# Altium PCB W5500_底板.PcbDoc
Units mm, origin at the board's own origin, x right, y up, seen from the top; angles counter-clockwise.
Board outline 58.8 x 115.4 mm, 2 copper layers (Top Layer, Bottom Layer); 79 components, 82 nets, 337 pads, 77 vias.
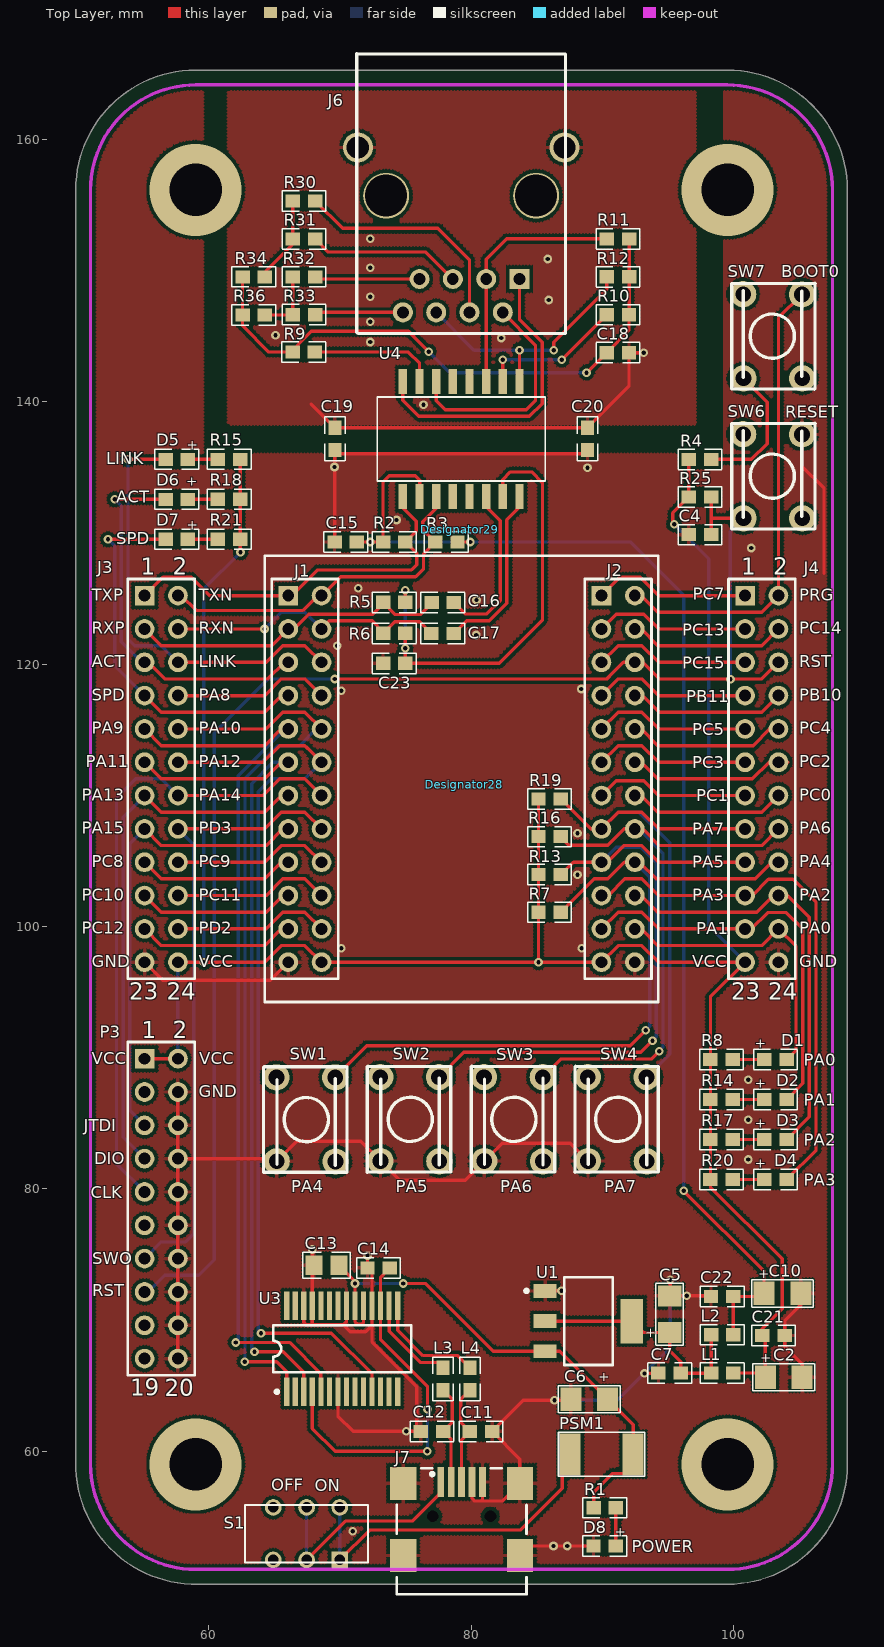
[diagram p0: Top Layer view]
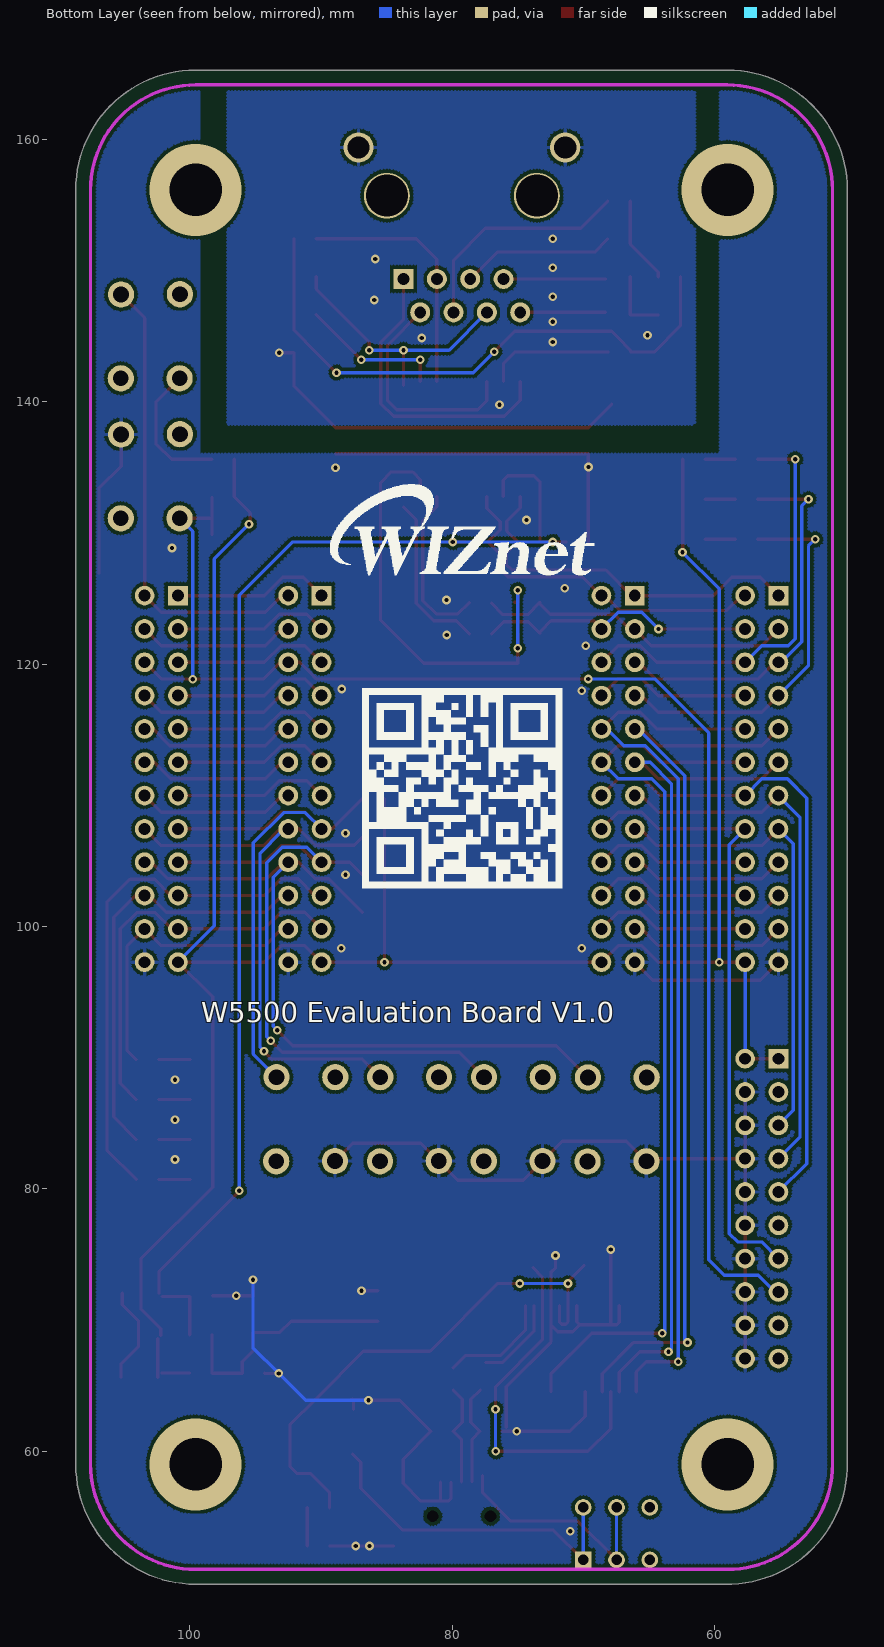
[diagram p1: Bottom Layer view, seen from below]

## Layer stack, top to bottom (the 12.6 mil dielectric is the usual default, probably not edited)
Top Layer: signal copper 0.0356
Dielectric: dielectric 0.32, FR-4, Dk 4.8
Bottom Layer: signal copper 0.0356

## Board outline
58.674,49.878 cw(c59,59) 49.878,58.674 cw(c50,58.712) 49.873,58.712 49.873,156.15 cw(c59,156.15) 59,165.277 99.55,165.277 cw(c99.55,156.15) 108.677,156.15 108.677,59 cw(c99.55,59) 99.55,49.873 58.712,49.873 cw(c58.712,50)

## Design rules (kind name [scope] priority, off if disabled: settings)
Clearance [All] p1: gap=0.254
FabricationTestPointUsage TestPointUsage [All] p1: valid=0 allowmultiple=FALSE
FabricationTestpoint Testpoint [All] p1: side=3 testpointundercomponent=TRUE minsize=1.016 maxsize=2.54 preferedsize=1.524 minholesize=0 maxholesize=1.016 preferedholesize=0.813 testpointgrid=0.025 allowsidetop=TRUE allowsidebottom=TRUE usegrid=TRUE gridtolerance=0
PolygonConnect PolygonConnect_1 [IsVia] p1: connectstyle=Direct reliefconductorwidth=0.254 reliefentries=4 polygonreliefangle="90 Angle"
PolygonConnect [All] p2: connectstyle=Relief reliefconductorwidth=0.254 reliefentries=4 polygonreliefangle="90 Angle"
RoutingVias [All] p1: holewidth=0.33 width=0.66 viastyle="Through Hole" minholewidth=0.33 minwidth=0.66 maxholewidth=0.33 maxwidth=0.66
SilkscreenOverComponentPads [All] p1: minsilkscreentomaskgap=0.254
SolderMaskExpansion [All] p1: expansion=0.102
Width [All] p1: maxlimit=0.254 minlimit=0.254 preferedwidth=0.254
25 further rules are at their usual default settings.

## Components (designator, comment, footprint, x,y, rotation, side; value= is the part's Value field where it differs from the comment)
C2 "Cap2" CR1206 103.886,65.608 r0 top
C4 "Cap" CR0603 97.409,129.998 r0 top
C5 "Cap2" CR1206 95.174,70.51 r90 top
C6 "Cap2" cr1206 88.951,64.008 r180 top
C7 "104" CR0603 95.174,65.83 r180 top
C10 "Cap2" CR1206 103.784,72.009 r0 top
C11 "Cap" CR0603 80.799,61.392 r180 top
C12 "Cap" CR0603 76.989,61.653 r0 top
C13 "Cap" CR0805 69.012,74.244 r0 top
C14 "Cap" CR0603 72.922,74.11 r0 top
C15 "Cap" CR0603 70.485,129.184 r180 top
C16 "Cap" CR0603 77.8,124.816 r0 top
C17 "Cap" CR0603 77.868,122.199 r180 top
C18 "Cap" CR0603 91.228,143.612 r180 top
C19 "1nF/2kV" CR0603 69.748,137.211 r270 top
C20 "1nF/2KV" CR0603 89.002,137.211 r270 top
C21 "104" CR0603 103.011,68.961 r0 top
C22 "104" CR0603 99.177,71.679 r180 top
C23 "Cap" CR0603 74.106,120.193 r0 top
D1 "蓝色" "CR0603 发光二极管" 103.249,89.863 r270 top
D2 "蓝色" "CR0603 发光二极管" 103.249,86.815 r270 top
D3 "蓝色" "CR0603 发光二极管" 103.249,83.767 r270 top
D4 "蓝色" "CR0603 发光二极管" 103.249,80.719 r270 top
D5 "绿色" "CR0603 发光二极管" 57.531,135.611 r90 top
D6 "黄色" "CR0603 发光二极管" 57.531,132.563 r90 top
D7 "绿色" "CR0603 发光二极管" 57.531,129.515 r90 top
D8 "红色" "CR0603 发光二极管" 90.145,52.781 r90 top
Designator28 "Comment" Wiznet微博二维码 79.477,110.82 r0 top
Designator29 "Comment" "Wiznet LOGO" 79.146,130.226 r0 top
J1 "2.0mm 间距插座 12x2" HDR2X12 66.067,125.222 r270 top locked
J2 "2.0mm 间距插座 12x2" HDR2X12 89.943,125.222 r270 top locked
J3 "2.54mm 间距插座 12x2" HDR2X12 55.118,125.222 r270 top locked
J4 "2.54mm 间距插座 12x2" HDR2X12 100.892,125.222 r270 top
J6 "RJ-45(不带变压器,不带灯)" RJ-45(SC902-5921S) 79.248,146.812 r180 top
J7 "MINI USB 接口" 440479 79.275,49.808 r270 top locked
L1 "Inductor" cr0603 99.109,66.091 r0 top
L2 "Inductor" cr0603 99.109,69.015 r0 top
L3 "Inductor" cr0603 77.724,65.481 r90 top
L4 "Inductor" cr0603 79.781,65.481 r90 top
P3 "2.54mm 间距 插针10X2" HDR2X10 55.118,89.928 r270 top
PSM1 "PSMIA" 保险管？ 87.554,59.766 r90 top
R1 "Res1" CR0603 90.153,55.829 r0 top
R2 "Res1" CR0603 74.184,129.191 r180 top
R3 "Res1" CR0603 78.078,129.438 r0 top
R4 "Res1" CR0603 97.409,135.738 r0 top
R5 "Res1" CR0603 74.106,124.841 r0 top
R6 "Res1" CR0603 74.106,122.479 r0 top
R7 "Res1" CR0603 85.954,101.219 r0 top
R8 "Res1" CR0603 99.058,89.99 r0 top
R9 "Res1" CR0603 67.208,143.916 r0 top
R10 "Res1" CR0603 91.228,146.502 r180 top
R11 "Res1" CR0603 91.161,152.542 r0 top
R12 "Res1" CR0603 91.161,149.652 r0 top
R13 "Res1" CR0603 85.954,104.098 r0 top
R14 "Res1" CR0603 99.058,86.942 r0 top
R15 "Res1" CR0603 61.595,135.484 r180 top
R16 "Res1" CR0603 85.954,106.976 r0 top
R17 "Res1" CR0603 99.058,83.894 r0 top
R18 "Res1" CR0603 61.595,132.436 r180 top
R19 "Res1" CR0603 85.954,109.855 r0 top
R20 "Res1" CR0603 99.058,80.846 r0 top
R21 "Res1" CR0603 61.595,129.388 r180 top
R25 "Res1" CR0603 97.409,132.868 r0 top
R30 "Res1" CR0603 67.31,155.169 r180 top
R31 "Res1" CR0603 67.31,152.281 r180 top
R32 "Res1" CR0603 67.31,149.394 r180 top
R33 "Res1" CR0603 67.31,146.507 r180 top
R34 "Res1" CR0603 63.475,149.394 r180 top
R36 "Res1" CR0603 63.475,146.482 r180 top
S1 "SW-SPDT" 单刀双路拨码 67.462,53.721 r180 top
SW1 "SW-SPST" 直插上位按键 66.215,84.562 r180 top
SW2 "SW-SPST" 直插上位按键 74.132,84.582 r180 top
SW3 "SW-SPST" 直插上位按键 82.04,84.582 r180 top
SW4 "SW-SPST" 直插上位按键 89.949,84.582 r180 top
SW6 "SW-SPST" 直插上位按键 104.191,135.052 r0 top
SW7 "SW-SPST" 直插上位按键 104.191,145.72 r0 top
U1 "LM1117-3.3" SOT-223 88.951,69.926 r270 top
U3 "FT232RL" SSOP28 70.18,67.818 r0 top locked
U4 "B-TRC1188" 11FB-05NL 79.248,137.16 r0 top locked

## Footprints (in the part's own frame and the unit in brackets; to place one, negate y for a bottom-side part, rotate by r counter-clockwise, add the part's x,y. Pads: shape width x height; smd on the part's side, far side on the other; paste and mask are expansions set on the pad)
11FB-05NL [mm] "11FB-05N"
  rect 0.635x1.91 smd: 1(-4.445,-4.38) 2(-3.175,-4.38) 3(-1.905,-4.38) 4(-0.635,-4.38) 5(0.635,-4.38) 6(1.905,-4.38) 7(3.175,-4.38) 8(4.445,-4.38) 9(4.445,4.38) 10(3.175,4.38) 11(1.905,4.38) 12(0.635,4.38) 13(-0.635,4.38) 14(-1.905,4.38) 15(-3.175,4.38) 16(-4.445,4.38)
  silkscreen extent -6.4,-3.2 6.4,3.2
440479 [mm]
  rect 2.3x0.5 smd: 1(-7.85,-1.6) 2(-7.85,-0.8) 3(-7.85,0) 4(-7.85,0.8) 5(-7.85,1.6)
  rect 2.5x2 smd: 6(-7.75,4.45) 7(-2.25,4.45) 8(-7.75,-4.45) 9(-2.25,-4.45)
  round 0.6 hole 0.9 unplated: MH1(-5.25,2.2) MH2(-5.25,-2.2)
  silkscreen extent -8.9,-4.95 0.7,4.95
CR0603 [mm]
  rect 1.1x1 smd: 1(-0.811,-0.127) 2(0.889,-0.127)
  silkscreen extent -1.63,-0.91 1.7,0.65
cr0603 [mm]
  rect 1.1x1 smd: 1(-0.811,-0.127) 2(0.889,-0.127)
  silkscreen extent -1.63,-0.91 1.7,0.65
"CR0603 发光二极管" [mm]
  rect 1x1.1 smd: 1(0,-0.887) 2(0,0.813)
  silkscreen extent -0.77,-1.71 0.78,1.63
CR0805 [mm]
  rect 1.3x1.5 smd: 1(-0.975,-0.051) 2(0.925,-0.051)
  silkscreen extent -1.85,-1.04 1.8,0.94
CR1206 [mm]
  rect 1.6x1.8 smd: 1(-1.453,0.035) 2(1.347,0.035)
  silkscreen extent -2.41,-1.01 2.3,1.08
cr1206 [mm]
  rect 1.6x1.8 smd: 1(-1.453,0.035) 2(1.347,0.035)
  silkscreen extent -2.41,-1.01 2.3,1.08
HDR2X10 [mm] "Connector; Header; 10x2 Positio"
  rect 1.5x1.5 hole 0.9: 1(0,0)
  round 1.5 hole 0.9: 2(0,2.54) 3(2.54,0) 4(2.54,2.54) 5(5.08,0) 6(5.08,2.54) 7(7.62,0) 8(7.62,2.54) 9(10.16,0) 10(10.16,2.54) 11(12.7,0) 12(12.7,2.54) 13(15.24,0) 14(15.24,2.54) 15(17.78,0) 16(17.78,2.54) 17(20.32,0) 18(20.32,2.54) 19(22.86,0) 20(22.86,2.54)
  silkscreen extent -1.27,-1.27 24.13,3.81
HDR2X12 [mm] "Connector; Header; 12x2 Position"
  rect 1.5x1.5 hole 0.9: 1(0,0)
  round 1.5 hole 0.9: 2(0,2.54) 3(2.54,0) 4(2.54,2.54) 5(5.08,0) 6(5.08,2.54) 7(7.62,0) 8(7.62,2.54) 9(10.16,0) 10(10.16,2.54) 11(12.7,0) 12(12.7,2.54) 13(15.24,0) 14(15.24,2.54) 15(17.78,0) 16(17.78,2.54) 17(20.32,0) 18(20.32,2.54) 19(22.86,0) 20(22.86,2.54) 21(25.4,0) 22(25.4,2.54) 23(27.94,0) 24(27.94,2.54)
  silkscreen extent -1.27,-1.27 29.21,3.81
RJ-45(SC902-5921S) [mm] "RJ-45(SC902-5921S"
  rect 1.524x1.524 hole 0.9: 1(-4.445,-2.54)
  round 1.524 hole 0.9: 2(-3.175,0) 3(-1.905,-2.54) 4(-0.635,0) 5(0.635,-2.54) 6(1.905,0) 7(3.175,-2.54) 8(4.445,0)
  round 2.3 hole 1.7: 9(-7.875,-12.57) 10(7.875,-12.57)
  round 3.5 hole 3.2: ""(-5.715,-8.89) ""(5.715,-8.89)
  silkscreen extent -7.95,-19.71 7.95,1.61
SOT-223 [mm] "SOT-223/SC-73; 4 Leads; Body 6.7 x 7.3 mm, inc. leads (LxW max"
  rect 1.05x1.75 smd: 1(-2.3,-3.3) 2(0,-3.3) 3(2.3,-3.3)
  rect 3.4x1.75 smd: 4(0,3.3)
  silkscreen extent -3.35,-4.85 3.35,1.85
SSOP28 [mm] "SSOP; 28 Leads; Body Width 5.3 mm; Pitch 0.65 m"
  rect 0.4x2.15 smd: 1(-4.225,-3.275) 2(-3.575,-3.275) 3(-2.925,-3.275) 4(-2.275,-3.275) 5(-1.625,-3.275) 6(-0.975,-3.275) 7(-0.325,-3.275) 8(0.325,-3.275) 9(0.975,-3.275) 10(1.625,-3.275) 11(2.275,-3.275) 12(2.925,-3.275) 13(3.575,-3.275) 14(4.225,-3.275) 15(4.225,3.275) 16(3.575,3.275) 17(2.925,3.275) 18(2.275,3.275) 19(1.625,3.275) 20(0.975,3.275) 21(0.325,3.275) 22(-0.325,3.275) 23(-0.975,3.275) 24(-1.625,3.275) 25(-2.275,3.275) 26(-2.925,3.275) 27(-3.575,3.275) 28(-4.225,3.275)
  silkscreen extent -5.25,-3.4 5.25,1.8
"Wiznet LOGO" [mm] "Wiznet LOGO"
Wiznet微博二维码 [mm] "Wi"
保险管？ [mm]
  rect 3.18x1.59 smd: 1(0,0) 2(0,-4.8)
  silkscreen extent -1.68,-5.69 1.68,0.89
单刀双路拨码 [mm]
  rect 1.27x1.27 hole 0.8: 1(-2.54,2)
  round 1.27 hole 0.8: 2(0,2) 3(2.54,2) 4(-2.54,-2) 5(0,-2) 6(2.54,-2)
  silkscreen extent -4.7,-2.2 4.7,2.2
直插上位按键 [mm]
  round 2 hole 1.2: 1(-3.429,-3.937) 2(1.051,-3.937) 3(1.031,2.453) 4(-3.449,2.473)
  silkscreen extent -4.33,-4.76 2.03,3.31

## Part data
C2 C4 C5 C6 C10 C11 C12 C14 C23: "Ca"
C7 C19 C20 C21 C22: library part CAP, "Ca"
C13: "Capacito"
C15 C16 C17 C18: library part Cap2, "Ca"
D1 D2 D3 D4 D5 D6 D7 D8: library part LED1, "Typical"
J1 J2 J3 J4: library part "Header 12X2", "Header, 12-Pin, Dual row"
J6: library part "Header 10", "Header, 10-Pin"
J7: library part 440479-2, "USB 2.0, Right Angle, SMT, AB Type, Receptacle, 5 Po"
L1 L2 L3 L4: "I"
P3: library part "Header 10X2", "Header, 10-Pin, Dual row"
PSM1: library part Res2, "Res"
R1 R4 R7 R8 R9 R10 R11 R12 R13 R14 R15 R16 R17 R18 R19 R20 R21 R25 R30 R31 R32 R33 R34 R36: "R"
R2 R3 R5 R6: library part Res3, "R"
S1: "SPDT Subminiature Toggle Switch, Right Angle Mounting, Vertical Actuation"
SW1 SW2 SW3 SW4 SW6 SW7: library part SW-PB
U1: library part REG1117-3.3, "800mA and 1A Low Dropout Positive Regulator 2.85V, 3.3V, 5V, and Adjustable"
U4: library part 11FB-05NL

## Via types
v1: diameter 0.66, hole 0.33, Top Layer to Bottom Layer, tented both sides, 73 vias
v2: diameter 7, hole 4, Top Layer to Bottom Layer, 4 vias

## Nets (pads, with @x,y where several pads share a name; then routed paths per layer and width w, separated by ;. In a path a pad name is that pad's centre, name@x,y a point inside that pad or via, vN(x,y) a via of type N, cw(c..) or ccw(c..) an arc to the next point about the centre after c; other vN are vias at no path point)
3V3: C14.2 U3.4 U3.17 | length 28.1
  Top Layer w0.254: U3.4 67.905,61.736 69.647,59.995 v1(76.657,59.995) v1@76.733,59.995 ; C14.2 73.105,73.278 U3.17 73.105,68.5 76.683,64.922 v1(76.683,63.195)
  Bottom Layer w0.254: v1@76.683,60.02 v1(76.683,63.195)
5V: C6.1 C13.2 PSM1.2 R1.1 U1.3 U3.19 U3.20 | length 40.7
  Top Layer w0.254: C13.2 71.155,72.975 v1(71.155,72.796) U3.20 71.155,69.891 71.349,69.698 71.653,69.698 71.805,69.849 U3.19 ; v1(74.828,72.796) 76.505,72.796 81.675,67.626 U1.3 86.75,67.626 C6.1 92.354,62.023 PSM1.2 92.354,58.851 91.812,58.31 90.771,58.31 89.342,56.881 R1.1
  Bottom Layer w0.254: v1(71.155,72.796) v1(74.828,72.796)
ACTLED: D6.2 J1.5 J3.5 | length 30.8
  Top Layer w0.254: v1(52.832,132.563) D6.2 ; J3.5 55.396,120.142 56.666,118.872 64.516,118.872 65.786,120.142 J1.5
  Bottom Layer w0.254: J3.5 54.908,120.142 53.34,121.71 53.34,132.055 ; v1(52.832,132.563) 53.34,132.055 ; v1(52.832,132.563) 53.34,132.055 ; v1(52.832,132.563) 53.34,132.055
AGND: C18.1 C19.1 C20.1 J6.9 J6.10 | length 29.8
  Top Layer w0.254: 67.816,139.827 C19.1 C20.1 92.039,141.187 C18.1 v1@92.964,143.739
  other v1: 76.378,139.776 93.167,143.739 72.314,144.551 82.296,144.856 65.1,145.059 72.314,146.101 85.928,147.752 72.314,148.006 72.314,150.216 85.852,150.876 72.314,152.425
BOOT0: J2.2 J4.2 SW7.3 | length 35.7
  Top Layer w0.254: J2.2 92.964,125.222 94.234,123.952 102.162,123.952 J4.2 103.432,146.383 SW7.3
CTS_USB: J1.12 J3.12 U3.11 | length 73.2
  Top Layer w0.254: J3.12 64.135,112.522 65.405,113.792 67.337,113.792 67.895,113.234 ; v1(63.986,69.012) 69.356,69.012 72.455,65.913 U3.11 ; 67.476,113.653 67.895,113.234 ; J1.12 67.895,113.234
  Bottom Layer w0.254: v1@63.783,69.063 63.783,84.938 ; 63.783,82.401 63.783,84.938 ; J1.12 67.337,111.252 64.77,111.252 63.783,110.265 63.783,84.938
D+: L4.2 U3.15 | length 8.5
  Top Layer w0.254: U3.15 74.405,69.232 76.336,67.301 78.977,67.301 L4.2
D-: L3.2 U3.16 | length 6.6
  Top Layer w0.254: U3.16 73.755,69.145 76.124,66.777 L3.2@77.445,66.777
GND: C2.2 C4.1 C5.2 C6.2 C7.2 C10.2 C11.1 C12.1 C13.1 C14.1 C15.2 C19.2 C20.2 C21.2 C22.2 C23.1 D8.2 J1.23 J2.24 J3.23 J4.24 J7.4 J7.5 J7.6 J7.7 J7.8 J7.9 P3.4 P3.6 P3.8 P3.10 P3.12 P3.14 P3.16 P3.18 P3.20 SW1.3 SW2.3 SW3.3 SW4.3 SW6.3 U1.1 U3.7 U3.18 U3.21 U3.25 U3.26 | length 196
  Top Layer w0.254: J3.23 56.49,95.91 64.695,95.91 J1.23 ; P3.20 P3.18 P3.16 P3.14 P3.12 P3.10 P3.8 ; P3.4 P3.6 P3.8 ; SW1.3@64.985,82.308 P3.8 ; SW1.3 66.718,83.642 71.587,83.642 SW2.3 74.559,80.67 79.551,80.67 SW3.3 82.37,83.49 87.557,83.49 SW4.3 ; U3.26 67.255,69.829 67.447,69.637 70.272,69.637 ; 67.742,69.647 67.905,69.81 U3.25 v1(67.905,75.387) ; C15.2@69.621,129.337 69.621,136.042 C20.2@88.875,136.042 ; U3.7 69.855,62.682 71.012,61.526 C12.1 ; U3.21 70.505,69.87 70.272,69.637 ; v1(72.111,74.93) C14.1 72.455,73.639 U3.18 72.455,69.61 ; C12.1@75.87,61.834 75.87,64.915 72.455,68.33 72.455,69.61 ; J7.4 80.075,56.425 80.289,56.21 80.747,56.21 ; J7.5 80.875,56.339 80.747,56.21 ; J7.7@84.448,52.781 D8.2 ; U1.1 85.662,72.238 v1(86.893,72.238) ; C6.2@87.512,63.191 C6.2@87.512,63.881 ; C6.2 C6.2@87.512,63.881 ; v1(93.218,65.938) 94.266,65.938 C7.2 ; C5.2 C22.2@98.236,71.858 ; v1(95.174,73.076) 95.174,72.028 C5.2@95.192,72.009 ; C10.2 105.132,71.172 103.9,69.941 C21.2 103.9,67.981 105.233,66.649 C2.2 ; SW6.3 105.222,135.094 106.909,133.407 106.909,126.924 ; 70.272,69.637 70.796,69.113 71.958,69.113 72.455,69.61 ; 80.747,56.21 82.377,56.21 J7.6 83.725,59.404 C11.1 83.972,63.881 v1(86.36,63.881) C6.2@87.512,63.881
  Bottom Layer w0.254: v1(86.36,63.881) 91.161,63.881 v1(93.218,65.938) 95.174,67.894 v1(95.174,73.076)
  other v1: 86.284,52.781 87.325,52.781 70.993,53.899 75.057,61.519 96.444,71.858 101.117,82.245 101.117,85.281 101.117,88.316 70.104,98.349 88.443,98.349 88.113,103.937 88.113,107.112 70.104,117.983 88.392,118.11 69.799,121.412 80.391,122.225 80.416,124.892 71.399,125.781 101.346,128.854 74.32,130.988 88.875,134.976 69.596,135.026
JTDI: J1.15 J3.15 P3.5 | length 35.5
  Top Layer w0.254: J3.15 56.388,106.172 64.389,106.172 65.659,107.442 J1.15
  Bottom Layer w0.254: P3.5 53.987,85.979 53.987,106.311 J3.15
LINKLED: D5.2 J1.6 J3.6 | length 33.1
  Top Layer w0.254: v1(53.848,135.611) D5.2 ; J3.6 64.389,120.142 65.659,121.412 67.337,121.412 J1.6
  Bottom Layer w0.254: v1(53.848,135.611) 53.848,121.92 54.356,121.412 56.388,121.412 J3.6
NetC11_2: C11.2 J7.3 L4.1 | length 8.2
  Top Layer w0.254: J7.3 79.275,60.096 ; 79.275,60.454 79.275,60.096 ; L4.1 79.223,63.984 79.223,62.206 C11.2 79.275,60.884 79.275,60.096
NetC12_2: C12.2 J7.2 L3.1 | length 7.8
  Top Layer w0.254: L3.1 78.562,63.959 78.562,62.21 C12.2 78.475,60.929 J7.2
NetC16_2: C16.2 U4.6 | length 12.7
  Top Layer w0.254: C16.2 79.553,123.825 81.197,123.825 82.22,124.848 82.22,130.937 81.153,132.004 U4.6
NetC17_1: C17.1 U4.8 | length 13.1
  Top Layer w0.254: C17.1 79.67,123.317 80.594,123.317 80.899,123.317 ; 81.28,123.317 80.899,123.317 ; U4.8@83.693,131.953 82.728,130.988 82.728,124.638 81.407,123.317 80.899,123.317
NetC18_2: C18.2 R9.1 R10.1 R11.2 R12.2 R34.2 R36.2 | length 45.9
  Top Layer w0.254: R34.2 R36.2 62.586,145.796 64.592,143.789 R9.1 66.397,143.944 67.285,144.831 ; 67.64,145.186 67.285,144.831 ; 75.413,145.186 76.124,144.475 ; v1(76.784,143.815) 76.124,144.475 ; v1(88.798,142.215) 88.815,142.215 C18.2 92.039,145.439 R10.1 92.05,146.639 R12.2 R11.2 ; 67.285,144.831 67.818,145.364 75.235,145.364 76.124,144.475
  Bottom Layer w0.254: v1(76.784,143.815) 78.384,142.215 v1(88.798,142.215)
NetC23_2: C23.2 R5.2 R6.2 U4.7 | length 36.3
  Top Layer w0.254: R6.2 v1(74.995,121.209) C23.2 82.169,120.066 85.446,123.342 85.446,133.833 84.633,134.645 83.007,134.645 82.423,134.061 U4.7 82.423,134.01 ; v1(74.995,125.642) R5.2 R5.2@75.209,124.714
  Bottom Layer w0.254: v1(74.995,121.209) v1(74.995,125.642)
NetD1_1: D1.1 R8.2 | length 2.4
  Top Layer w0.254: R8.2@99.948,89.863 D1.1
NetD2_1: D2.1 R14.2 | length 2.4
  Top Layer w0.254: R14.2@99.948,86.815 D2.1
NetD3_1: D3.1 R17.2 | length 2.4
  Top Layer w0.254: R17.2@99.948,83.767 D3.1
NetD4_1: D4.1 R20.2 | length 2.4
  Top Layer w0.254: R20.2@99.948,80.719 D4.1
NetD5_1: D5.1 R15.2 | length 2.3
  Top Layer w0.254: D5.1 R15.2
NetD6_1: D6.1 R18.2 | length 2.3
  Top Layer w0.254: D6.1 R18.2
NetD7_1: D7.1 R21.2 | length 2.3
  Top Layer w0.254: D7.1 R21.2
NetD8_1: D8.1 R1.2 | length 2.9
  Top Layer w0.254: D8.1 R1.2@91.032,55.692
NetJ6_4: J6.4 R30.1 | length 17.6
  Top Layer w0.254: R30.1 70.204,153.213 77.47,153.213 79.883,150.8 J6.4
NetJ6_5: J6.5 R31.1 | length 11.8
  Top Layer w0.254: R31.1 68.155,152.375 69.12,151.409 76.556,151.409 J6.5
NetJ6_7: J6.7 R32.1 | length 7.8
  Top Layer w0.254: R32.1@68.29,149.352 J6.7
NetJ6_8: J6.8 R33.1 | length 6.5
  Top Layer w0.254: R33.1@68.299,146.812 J6.8
NetPSM1_1: PSM1.1 S1.1 | length 26
  Top Layer w0.254: S1.1 72.282,54 83.769,54 86.944,57.175 86.944,59.157 PSM1.1
  Bottom Layer w0.254: S1.1 70.002,55.721
NetR4_2: R4.2 SW7.1 | length 10.5
  Top Layer w0.254: R4.2 101.372,135.611 102.565,136.804 102.565,139.979 SW7.1
NetR9_2: R9.2 U4.15 | length 9.7
  Top Layer w0.254: R9.2 75.209,143.789 76.073,142.926 U4.15
NetR10_2: R10.2 U4.10 | length 11
  Top Layer w0.254: U4.10 v1(82.423,143.205) ; v1(86.919,143.205) 90.339,146.626 R10.2
  Bottom Layer w0.254: v1(82.423,143.205) v1(86.919,143.205)
NetR30_2: R30.2 R31.2 R34.1 | length 6.7
  Top Layer w0.254: R34.1 64.286,149.884 66.421,152.019 R31.2 R30.2
NetR32_2: R32.2 R33.2 R36.1 | length 5
  Top Layer w0.254: R36.1 R33.2@66.396,146.609 ; R33.2 R32.2
NRESET: C4.2 J2.6 J4.6 P3.15 R25.2 SW6.1 | length 111.4
  Top Layer w0.254: v1(69.621,118.872) 90.348,118.872 90.82,119.344 ; 90.373,118.897 90.82,119.344 ; C4.2 R25.2 ; 98.349,131.115 SW6.1 ; J4.6 102.162,118.872 99.873,118.872 94.361,118.872 93.091,120.142 J2.6 91.618,120.142 90.82,119.344
  Bottom Layer w0.254: P3.15 55.396,72.148 56.666,73.418 58.493,73.418 59.245,73.418 60.427,74.6 60.427,114.757 64.541,118.872 v1(69.621,118.872) ; v1(99.771,118.847) 99.797,118.872 99.797,118.948 99.761,118.984 99.761,130.114 SW6.1
PA0: D1.2 J2.22 J4.22 | length 22.8
  Top Layer w0.254: J2.22 92.964,99.822 94.234,98.552 102.162,98.552 J4.22 104.775,98.479 104.775,90.576 D1.2
PA1: D2.2 J2.21 J4.21 | length 30.9
  Top Layer w0.254: J2.21 91.213,101.092 93.028,101.092 94.298,99.822 J4.21 101.371,99.822 102.616,101.067 104.038,101.067 105.283,99.822 105.283,88.036 D2.2
PA2: D3.2 J2.20 J4.20 | length 31.1
  Top Layer w0.254: J2.20 92.964,102.362 94.234,101.092 101.778,101.092 102.718,102.032 ; D3.2 105.791,85.496 105.791,100.711 105.181,101.321 J4.20@104.14,102.362
PA3: D4.2 J2.19 J4.19 | length 40.7
  Top Layer w0.254: J2.19 90.449,102.362 91.719,103.632 93.028,103.632 94.298,102.362 J4.19 101.422,102.362 102.667,103.607 104.546,103.607 106.299,101.854 106.299,82.956 D4.2
PA4: J2.18 J4.18 R7.2 SW1.1 | length 58.2
  Top Layer w0.254: SW1.1 72.061,90.916 92.135,90.916 v1(93.32,92.1) ; R7.2 89.383,103.632 90.424,103.632 91.694,104.902 J2.18 92.837,104.902 94.107,103.632 101.651,103.632 102.921,104.902 J4.18
  Bottom Layer w0.254: J2.18 93.614,103.771 93.614,92.395 ; 93.614,92.395 v1(93.32,92.1) 93.614,92.395
PA5: J2.17 J4.17 R13.2 SW2.1 | length 53.7
  Top Layer w0.254: SW2.1 79.45,90.408 81.382,90.408 92.935,90.408 v1(93.828,91.3) ; R13.2@86.843,103.937 87.808,104.902 J2.17 ; 88.443,104.902 J2.17 ; J4.17 94.298,104.902 93.028,106.172 91.643,106.172 90.373,104.902 J2.17
  Bottom Layer w0.254: J2.17 91.074,106.033 92.951,106.033 94.122,104.862 94.122,91.595 v1(93.828,91.3) ; v1@93.828,91.313 94.122,91.607
PA6: J2.16 J4.16 R16.2 SW3.1 | length 46.7
  Top Layer w0.254: SW3.1 86.85,89.9 93.735,89.9 v1(94.336,90.5) ; R16.2@86.843,106.807 87.452,106.197 89.357,106.197 ; 88.875,106.197 89.357,106.197 ; J4.16 102.162,106.172 94.361,106.172 93.091,107.442 J2.16 91.669,107.442 90.424,106.197 89.357,106.197
  Bottom Layer w0.254: J2.16 92.697,107.228 93.001,107.228 94.63,105.598 94.63,90.795 v1(94.336,90.5)
PA7: J2.15 J4.15 R19.2 SW4.1 | length 41.8
  Top Layer w0.254: R19.2 89.129,107.442 J2.15 ; J2.15@89.459,107.442 J2.15 ; J4.15 94.298,107.442 93.028,108.712 91.213,108.712 J2.15
  Bottom Layer w0.254: J2.15 91.188,108.687 92.838,108.687 95.138,106.386 95.138,90.279 SW4.1
PA8: J1.8 J3.8 | length 12
  Top Layer w0.254: J3.8 64.262,117.602 65.532,118.872 67.337,118.872 J1.8
PA9: J1.9 J3.9 U3.5 | length 70.1
  Top Layer w0.254: J3.9 56.388,113.792 64.262,113.792 65.532,115.062 65.957,115.062 J1.9 ; v1(62.056,68.301) 65.761,68.301 66.167,68.301 68.555,65.912 U3.5
  Bottom Layer w0.254: v1(62.056,68.301) 62.259,68.504 62.259,83.718 ; 62.259,83.033 62.259,83.718 ; J1.9 65.83,115.062 62.259,111.492 62.259,83.718
PA10: J1.10 J3.10 U3.1 | length 69.8
  Top Layer w0.254: J3.10 64.389,115.062 65.659,116.332 67.337,116.332 J1.10 ; v1(62.763,66.827) 65.176,66.827 65.955,66.049 U3.1
  Bottom Layer w0.254: v1@62.767,66.802 62.767,83.668 ; 62.767,82.822 62.767,83.668 ; J1.10 68.199,115.062 66.929,113.792 65.278,113.792 62.767,111.281 62.767,83.668
PA11: J1.11 J3.11 U3.3 | length 64.7
  Top Layer w0.254: J3.11 56.388,111.252 64.262,111.252 65.532,112.522 65.957,112.522 J1.11 ; v1(63.5,67.589) 65.68,67.589 67.255,66.015 U3.3
  Bottom Layer w0.254: v1(63.5,67.589) 63.275,67.814 63.275,110.9 64.897,112.522 J1.11
PA13: J1.13 J3.13 P3.7 | length 41.4
  Top Layer w0.254: J3.13 55.98,109.12 ; 56.261,108.839 55.98,109.12 ; J1.13 65.532,109.982 64.262,108.712 56.388,108.712 55.98,109.12
  Bottom Layer w0.254: P3.7 53.479,83.947 53.479,108.343 J3.13
PA14: J1.14 J3.14 P3.9 | length 48.7
  Top Layer w0.254: J3.14 64.135,109.982 65.405,111.252 67.337,111.252 J1.14
  Bottom Layer w0.254: P3.9 52.971,81.915 52.971,109.794 54.429,111.252 56.388,111.252 J3.14
PB10: J2.8 J4.8 | length 12
  Top Layer w0.254: J2.8 93.091,117.602 94.361,116.332 102.162,116.332 J4.8
PB11: J2.7 J4.7 | length 12
  Top Layer w0.254: J2.7 91.213,118.872 93.028,118.872 94.298,117.602 J4.7
PC0: J2.14 J4.14 | length 12
  Top Layer w0.254: J2.14 92.964,109.982 94.234,108.712 102.162,108.712 J4.14
PC1: J2.13 J4.13 | length 11.9
  Top Layer w0.254: J2.13 91.074,111.113 93.174,111.113 94.305,109.982 ; 94.298,109.982 94.305,109.982 ; J4.13 94.305,109.982
PC2: J2.12 J4.12 | length 12
  Top Layer w0.254: J2.12 92.964,112.522 94.234,111.252 101.444,111.252 J4.12@102.714,112.522 ; J4.12 J4.12@104.14,112.522
PC3: J2.11 J4.11 | length 12
  Top Layer w0.254: J2.11 91.213,113.792 93.028,113.792 94.298,112.522 J4.11
PC4: J2.10 J4.10 | length 12
  Top Layer w0.254: J2.10 92.964,115.062 94.234,113.792 101.517,113.792 102.787,115.062 J4.10
PC5: J2.9 J4.9 | length 12
  Top Layer w0.254: J2.9 91.213,116.332 93.028,116.332 94.298,115.062 94.488,115.062 J4.9
PC7: J2.1 J4.1 | length 12.1
  Top Layer w0.254: J2.1 91.34,126.619 92.901,126.619 94.298,125.222 J4.1
PC8: J1.17 J3.17 | length 12
  Top Layer w0.254: J3.17 56.388,103.632 64.262,103.632 65.532,104.902 J1.17
PC9: J1.18 J3.18 | length 12
  Top Layer w0.254: J3.18 64.262,104.902 65.532,106.172 67.337,106.172 J1.18
PC10: J1.19 J3.19 | length 12
  Top Layer w0.254: J3.19 56.388,101.092 64.389,101.092 65.659,102.362 J1.19
PC11: J1.20 J3.20 | length 12
  Top Layer w0.254: J3.20 64.389,102.362 65.659,103.632 67.337,103.632 J1.20
PC12: J1.21 J3.21 | length 12
  Top Layer w0.254: J3.21 56.388,98.552 64.262,98.552 65.532,99.822 J1.21
PC13: J2.3 J4.3 | length 11.9
  Top Layer w0.254: J2.3 91.074,123.813 93.167,123.813 94.298,122.682 J4.3
PC14: J2.4 J4.4 | length 12
  Top Layer w0.254: J2.4 92.964,122.682 94.234,121.412 102.162,121.412 J4.4
PC15: J2.5 J4.5 | length 12
  Top Layer w0.254: J2.5 91.213,121.412 93.028,121.412 94.298,120.142 94.488,120.142 J4.5
PD2: J1.22 J3.22 | length 12
  Top Layer w0.254: J3.22 64.389,99.822 65.659,101.092 67.337,101.092 J1.22
PD3: J1.16 J3.16 P3.13 | length 47.9
  Top Layer w0.254: J3.16 64.262,107.442 65.532,108.712 67.337,108.712 J1.16
  Bottom Layer w0.254: P3.13 56.388,75.958 58.239,75.958 58.874,76.593 58.874,106.226 J3.16
RXIN: J6.6 R12.1 U4.9 | length 20.1
  Top Layer w0.254: U4.9@83.693,141.249 U4.9 v1(83.693,143.931) ; v1(86.309,143.931) 86.309,144.551 90.35,148.592 R12.1
  Bottom Layer w0.254: J6.6 80.224,143.931 v1(83.693,143.931) v1(86.309,143.931)
RXIP: J6.3 R11.1 U4.11 | length 19.2
  Top Layer w0.254: U4.11 J6.3 81.153,150.851 82.718,152.415 R11.1
RXN: C17.2 J1.4 J3.4 R6.1 | length 21.7
  Top Layer w0.254: J3.4 v1(64.262,122.682) ; J1.4 68.607,122.709 69.203,123.305 72.458,123.305 R6.1@73.285,122.479 ; R6.1 74.176,123.233 76.073,123.233 C17.2
  Bottom Layer w0.254: v1(64.262,122.682) 65.532,123.952 67.337,123.952 J1.4
RXP: C16.1 J1.3 J3.3 R5.1 | length 25
  Top Layer w0.254: J3.3 55.853,121.947 ; 56.249,121.551 55.853,121.947 ; R5.1@73.295,124.587 72.521,123.813 67.638,123.813 66.507,122.682 J1.3 64.797,121.412 56.388,121.412 55.853,121.947 ; R5.1 74.227,123.782 76.134,123.782 C16.1@76.989,124.638
SPDLED: D7.2 J1.7 J3.7 | length 30.9
  Top Layer w0.254: v1(52.324,129.515) D7.2 ; J3.7 56.388,116.332 64.262,116.332 65.532,117.602 J1.7
  Bottom Layer w0.254: J3.7 52.832,119.888 52.832,129.007 ; v1(52.324,129.515) 52.832,129.007 ; v1(52.324,129.515) 52.832,129.007 ; v1(52.324,129.515) 52.832,129.007
TXN: J1.2 J3.2 R3.1 U4.3 | length 27.2
  Top Layer w0.254: J3.2 57.912,125.222 59.043,124.091 67.198,124.091 68.329,125.222 J1.2 70.055,126.67 75.768,126.67 76.378,127.279 76.378,128.422 R3.1 76.327,130.251 76.327,130.861 77.343,131.877 U4.3
TXON: J6.2 U4.14 | length 17.4
  Top Layer w0.254: U4.14 77.343,140.081 78.029,139.395 84.226,139.395 84.912,140.081 84.912,144.323 J6.2
TXOP: J6.1 U4.16 | length 23.2
  Top Layer w0.254: U4.16 74.803,140.106 76.022,138.887 84.455,138.887 85.42,139.852 85.42,144.551 83.693,146.279 J6.1
TXP: J1.1 J3.1 R2.1 U4.1 | length 29.2
  Top Layer w0.254: J3.1 56.515,126.619 58.674,126.619 60.071,125.222 J1.1 66.345,125.222 68.301,127.178 75.463,127.178 75.87,127.584 75.87,128.443 R2.1 75.819,130.142 75.819,130.886 74.803,131.902 U4.1
V3.3: C5.1 C7.1 L1.1 L2.1 U1.2 U1.4 | length 18.5
  Top Layer w0.254: U1.2 U1.4 93.119,69.058 C5.1 95.139,67.675 95.985,66.829 C7.1 98.291,65.957 L1.1 L2.1
VCC: C2.1 C21.1 J1.24 J2.23 J3.24 J4.23 L1.2 P3.1 P3.2 R4.1 R7.1 R8.1 R13.1 R14.1 R15.1 R16.1 R17.1 R18.1 R19.1 R20.1 R21.1 R25.1 | length 186.3
  Top Layer w0.254: P3.1 P3.2 ; J3.24 v1(59.639,97.282) 64.262,97.282 65.532,98.552 67.337,98.552 J1.24 J2.23 91.213,98.552 93.028,98.552 94.298,97.282 J4.23 98.247,94.637 R8.1@98.247,89.408 ; v1@62.406,128.524 R21.1 R18.1 R15.1 ; v1(85.143,97.284) R7.1 85.143,103.937 85.143,106.807 R19.1 ; v1@95.377,130.658 95.377,131.52 R25.1 R4.1 ; R20.1@98.247,80.592 R20.1 ; R8.1 R14.1 R17.1 R20.1 ; L1.2 C2.1@102.113,65.964 ; C21.1 102.2,69.358 103.708,70.866 103.708,74.676 98.247,80.137 R20.1 ; C2.1 C21.1@102.433,68.601
  Bottom Layer w0.254: P3.2 J3.24 ; v1(59.639,97.282) 59.639,125.73 v1(62.433,128.524) ; v1(95.479,130.658) 98.12,128.017 98.12,100.054 J4.23
VCCA: C10.1 C15.1 C22.1 L2.2 R2.2 R3.2 U4.2 | length 98.7
  Top Layer w0.254: C15.1 v1(72.314,129.311) R2.2@73.288,129.311 ; R2.2 73.295,133.899 73.762,134.366 75.743,134.366 76.098,134.01 76.098,132.805 U4.2 ; R3.2 v1(79.934,129.311) ; v1(96.222,79.858) 96.222,79.825 102.332,73.716 C10.1 ; C22.1 C10.1@102.093,71.806 ; L2.2 C22.1@99.998,71.796
  Bottom Layer w0.254: v1(72.314,129.311) v1(79.934,129.311) 86.69,129.311 ; 87.097,129.311 86.69,129.311 ; v1@96.221,79.858 96.221,125.242 92.151,129.311 86.69,129.311
VUSB: J7.1 S1.2 | length 17.6
  Top Layer w0.254: S1.2 70.428,54.686 75.528,54.686 77.675,56.833 J7.1 J7.1@77.675,58.139
  Bottom Layer w0.254: S1.2 67.462,55.721
pads on no net: J6. J7.MH1 J7.MH2 P3.3 P3.11 P3.17 P3.19 S1.3 S1.4 S1.5 S1.6 SW1.2 SW1.4 SW2.2 SW2.4 SW3.2 SW3.4 SW4.2 SW4.4 SW6.2 SW6.4 SW7.2 SW7.4 U3.2 U3.6 U3.8 U3.9 U3.10 U3.12 U3.13 U3.14 U3.22 U3.23 U3.24 U3.27 U3.28 U4.4 U4.5 U4.12 U4.13
copper on no net:
  other v1: 59,59 59,59
  other v2: 59,59 99.55,59 59,156.15 99.55,156.15

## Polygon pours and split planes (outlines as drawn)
AGND on Top Layer "Bottom Layer-No Net" (hatched 90Degree grid 0 track 0.254, remove dead copper, pour order 1000): 97.104,138.278 61.488,138.278 61.488,164.926 61.443,164.998 97.057,164.998 97.088,164.948
GND on Top Layer "Bottom Layer-No Net" (hatched 90Degree grid 0 track 0.254, remove dead copper, pour order 1001): 59.563,164.15 59.563,136.042 59.512,135.992 99.314,135.992 99.314,164.15 107.711,164.15 107.798,164.236 107.798,50.038 107.823,50.013 50.546,50.013 50.216,50.343 50.216,164.084 50.292,164.16
AGND on Bottom Layer "Bottom Layer-No Net" (hatched 90Degree grid 0 track 0.254, remove dead copper, pour order 1002): 97.104,138.278 61.488,138.278 61.488,164.926 61.443,164.998 97.057,164.998 97.088,164.948
GND on Bottom Layer "Bottom Layer-No Net" (hatched 90Degree grid 0 track 0.254, remove dead copper, pour order 1003): 59.563,164.15 59.563,136.042 59.512,135.992 99.314,135.992 99.314,164.15 107.711,164.15 107.798,164.236 107.798,50.038 107.823,50.013 50.546,50.013 50.216,50.343 50.216,164.084 50.292,164.16

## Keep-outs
Keep-Out Layer:
  lines w0.254: 51,58.712 51,156.15 cw(c59,156.15) 59,164.15 99.55,164.15 cw(c99.55,156.15) 107.55,156.15 107.55,59 cw(c99.55,59) 99.55,51 58.712,51 ; 51,59 ccw(c59,59) 59,51

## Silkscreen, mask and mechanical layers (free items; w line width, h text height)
Top Overlay:
  lines w0.203: 64.277,94.253 94.273,94.253 94.273,128.27 ; 64.277,94.31 64.277,128.168 ; 64.289,128.251 94.273,128.251
  text "BOOT0" at 103.632,149.504 h0.91
  text "RESET" at 103.94,138.786 h0.91
  text "LINK" at 52.197,135.23 h0.91
  text "ACT" at 52.959,132.309 h0.91
  text "SPD" at 52.959,129.134 h0.91
  text "PC7" at 96.901,124.892 h0.91
  text "TXP" at 51.075,124.841 h0.91
  text "TXN" at 59.255,124.841 h0.91
  text "PRG" at 105.029,124.841 h0.91
  text "RXP" at 51.075,122.301 h0.91
  text "RXN" at 59.255,122.301 h0.91
  text "PC14" at 105.029,122.301 h0.91
  text "PC13" at 96.088,122.162 h0.91
  text "ACT" at 51.075,119.761 h0.91
  text "LINK" at 59.255,119.761 h0.91
  text "RST" at 105.029,119.761 h0.91
  text "PC15" at 96.088,119.636 h0.91
  text "SPD" at 51.075,117.221 h0.91
  text "PA8" at 59.255,117.221 h0.91
  text "PB10" at 105.029,117.221 h0.91
  text "PB11" at 96.393,117.11 h0.91
  text "PA9" at 51.075,114.681 h0.91
  text "PA10" at 59.255,114.681 h0.91
  text "PC4" at 105.029,114.681 h0.91
  text "PC5" at 96.85,114.584 h0.91
  text "PA11" at 50.618,112.141 h0.91
  text "PA12" at 59.255,112.141 h0.91
  text "PC2" at 105.029,112.141 h0.91
  text "PC3" at 96.85,112.058 h0.91
  text "PA13" at 50.314,109.601 h0.91
  text "PA14" at 59.255,109.601 h0.91
  text "PC0" at 105.029,109.601 h0.91
  text "PC1" at 97.155,109.532 h0.91
  text "PA15" at 50.314,107.061 h0.91
  text "PD3" at 59.255,107.061 h0.91
  text "PA6" at 105.029,107.061 h0.91
  text "PA7" at 96.85,107.006 h0.91
  text "PC8" at 51.075,104.521 h0.91
  text "PC9" at 59.255,104.521 h0.91
  text "PA4" at 105.029,104.521 h0.91
  text "PA5" at 96.85,104.479 h0.91
  text "PC10" at 50.314,101.981 h0.91
  text "PC11" at 59.255,101.981 h0.91
  text "PA2" at 105.029,101.981 h0.91
  text "PA3" at 96.85,101.953 h0.91
  text "PC12" at 50.314,99.441 h0.91
  text "PD2" at 59.255,99.441 h0.91
  text "PA0" at 105.029,99.441 h0.91
  text "PA1" at 97.155,99.427 h0.91
  text "GND" at 51.075,96.901 h0.91
  text "VCC" at 59.255,96.901 h0.91
  text "VCC" at 96.85,96.901 h0.91
  text "GND" at 105.029,96.901 h0.91
  text "VCC" at 51.079,89.51 h0.91
  text "VCC" at 59.283,89.51 h0.91
  text "PA0" at 105.378,89.383 h0.91
  text "GND" at 59.258,86.97 h0.91
  text "PA1" at 105.378,86.335 h0.91
  text "JTDI" at 50.47,84.379 h0.91
  text "PA2" at 105.378,83.287 h0.91
  text "DIO" at 51.283,81.864 h0.91
  text "PA3" at 105.378,80.239 h0.91
  text "PA4" at 66.294,79.756 h0.91
  text "PA5" at 74.253,79.756 h0.91
  text "PA6" at 82.211,79.756 h0.91
  text "PA7" at 90.17,79.756 h0.91
  text "CLK" at 51,79.299 h0.91
  text "SWO" at 51.126,74.244 h0.91
  text "RST" at 51.126,71.806 h0.91
  text "OFF" at 64.77,56.998 h0.91
  text "ON" at 68.072,56.972 h0.91
  text "POWER" at 92.253,52.324 h0.91
Bottom Overlay:
  text "W5500 Evaluation Board V1.0" at 99.111,92.71 h1.52
Mechanical 1:
  lines w0.254: 50,58.712 50,156.15 cw(c59,156.15) 59,165.15 99.55,165.15 cw(c99.55,156.15) 108.55,156.15 108.55,59 cw(c99.55,59) 99.55,50 58.712,50 ; 50,59 ccw(c59,59) 59,50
